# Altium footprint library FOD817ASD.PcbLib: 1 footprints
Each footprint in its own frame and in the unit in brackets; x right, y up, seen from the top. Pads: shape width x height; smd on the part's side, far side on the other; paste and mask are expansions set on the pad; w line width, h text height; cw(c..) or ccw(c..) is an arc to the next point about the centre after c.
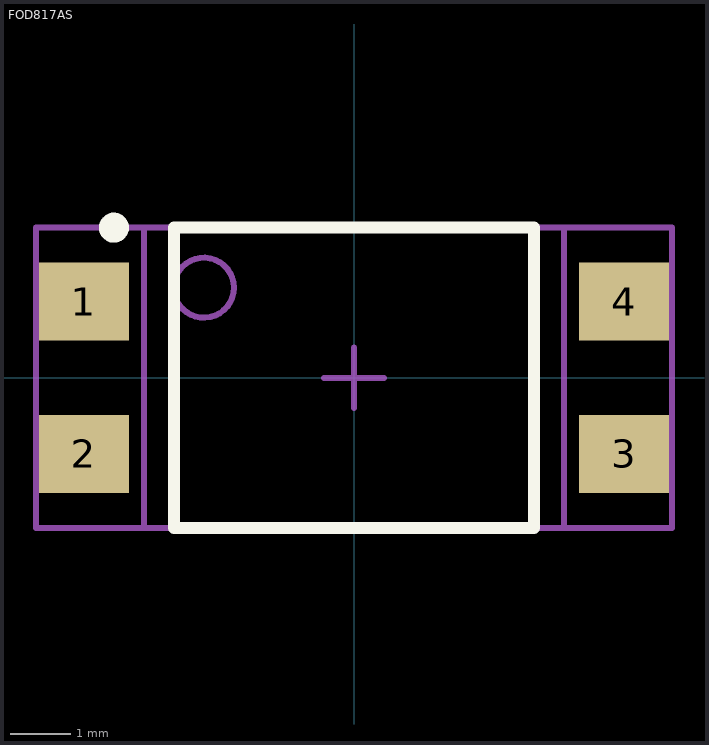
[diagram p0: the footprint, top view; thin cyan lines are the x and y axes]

## FOD817AS [mm] "FOD817AS recommended footprint"
height 4
pads (4):
  rect 1.5x1.3 smd: 1(-4.5,1.27) 2(-4.5,-1.27) 3(4.5,-1.27) 4(4.5,1.27)
Top Overlay:
  circle w0.25: c-4,2.5 r0.125
  lines w0.2: -3,-2.5 3,-2.5 3,2.5 -3,2.5 -3,-2.5
Mechanical 5:
  text ".Designator" at -1.524,-0.508 h1.02
Mechanical 13:
  circle w0.1: c-2.5,1.5 r0.5
  lines w0.1: -3.5,-2.5 3.5,-2.5 3.5,2.5 -3.5,2.5 -3.5,-2.5
Mechanical 15:
  lines w0.1: -0.5,0 0.5,0 ; 0,-0.5 0,0.5 ; -5.3,-2.5 5.3,-2.5 5.3,2.5 -5.3,2.5 -5.3,-2.5
3D body: height 4, standoff 0, extent -3.009,0.991 -1.991,2.009
3D body: height 4, standoff 0, extent -3.5,-2.5 3.5,2.5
